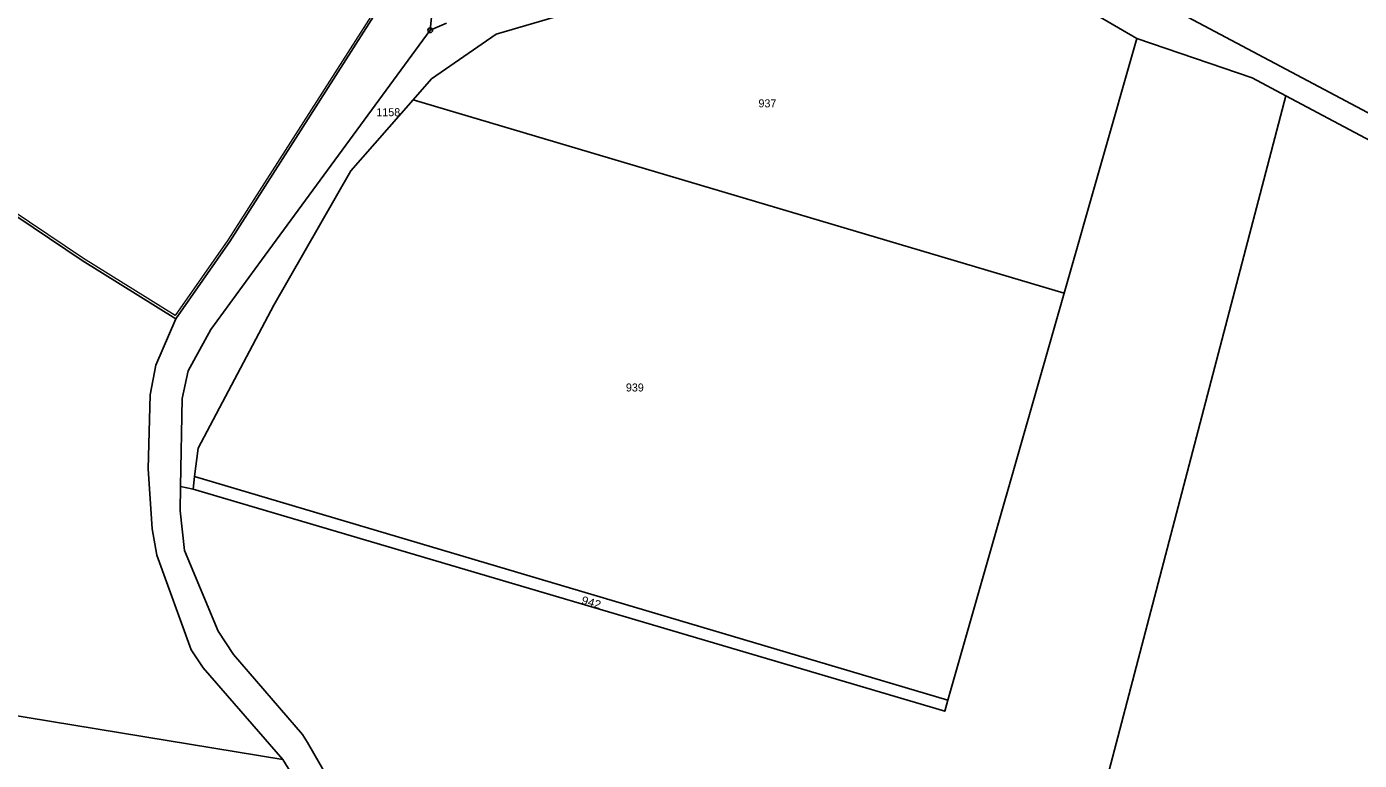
# Model space of a CAD drawing. Extents: x -758887 to -754328, y -1031688 to -1029144.
# Drawn here: x -756703.8 to -756420.8, y -1031001.8 to -1030846 of the extents above; entities that cross this region are included whole.
import ezdxf
from ezdxf.enums import TextEntityAlignment as Align

# ---------------------------------------------------------------- set-up
doc = ezdxf.new("R2010")
doc.units = 0
doc.header["$LTSCALE"] = 0.68
for name, color, linetype, lineweight in [('1', 7, 'Continuous', 25), ('4', 7, 'Continuous', 13), ('8', 7, 'Continuous', 25)]:
    doc.layers.add(name, color=color, linetype=linetype, lineweight=lineweight)
doc.layers.add('2', color=7, linetype='Continuous')

msp = doc.modelspace()

# ---------------------------------------------------------------- linework, layer by layer
at = {"layer": '1'}
for p, q in [((-756468.05, -1030848.51), (-756494.5, -1030833.17)), ((-756468.07, -1030838.25), (-756377.14, -1030886.55)), ((-756483.51, -1030902.61), (-756468.05, -1030848.51)), ((-756483.51, -1030902.61), (-756508.2, -1030989.01)), ((-756668.21, -1030941.54), (-756668.46, -1030944.22)), ((-756668.21, -1030941.54), (-756508.2, -1030989.01))]:
    msp.add_line(p, q, dxfattribs=at)
for points in [[(-756672.17, -1030908.07), (-756660.72, -1030891.63), (-756626.91, -1030838.7), (-756614.56, -1030811.5)], [(-756614.56, -1030811.5), (-756618.14, -1030846.79), (-756614.71, -1030845.27)], [(-756786.29, -1030838.32), (-756764.35, -1030847.07), (-756692.05, -1030895.68), (-756672.17, -1030908.07)], [(-756583.54, -1030841.59), (-756604.14, -1030847.6), (-756617.85, -1030857.11), (-756621.79, -1030861.59), (-756483.51, -1030902.61)], [(-756618.14, -1030846.79), (-756653.98, -1030895.62), (-756664.7, -1030910.36), (-756669.57, -1030919.12), (-756670.82, -1030924.96), (-756671.15, -1030943.68)], [(-756436.41, -1030860.73), (-756443.59, -1030856.91), (-756468.05, -1030848.51)], [(-756621.79, -1030861.59), (-756635.01, -1030876.63), (-756651.34, -1030905.15), (-756667.41, -1030935.53), (-756668.21, -1030941.54)], [(-756536.4, -1031242.21), (-756486.41, -1031051.47), (-756436.41, -1030860.73)], [(-756441.29, -1031306.34), (-756406.04, -1031176.45), (-756367.75, -1031046.99), (-756329.46, -1030917.53), (-756436.41, -1030860.73)], [(-756649.43, -1031001.63), (-756666.33, -1030982.19), (-756668.89, -1030978.32), (-756676.21, -1030958.25), (-756677.16, -1030952.66), (-756678.05, -1030939.95), (-756677.6, -1030924.23), (-756676.42, -1030917.94), (-756672.17, -1030908.07)], [(-756671.15, -1030943.68), (-756671.24, -1030948.87), (-756670.29, -1030957.24), (-756663.15, -1030974.42), (-756659.93, -1030979.33), (-756645.28, -1030996.35), (-756644.17, -1030998.05), (-756635.1, -1031013.91), (-756640.03, -1031033.6), (-756650.92, -1031058.77), (-756657.64, -1031094.12), (-756675.96, -1031141.39), (-756688.89, -1031194.83), (-756695.71, -1031217.52), (-756536.4, -1031242.21)], [(-756508.2, -1030989.01), (-756508.85, -1030991.38), (-756668.46, -1030944.22), (-756671.15, -1030943.68)], [(-756833.28, -1030963.17), (-756748.2, -1030985.46), (-756649.43, -1031001.63)], [(-756651.64, -1031045.32), (-756645.73, -1031031.66), (-756642.99, -1031020.25), (-756644.38, -1031009.77), (-756649.43, -1031001.63)]]:
    msp.add_lwpolyline(points, dxfattribs=at)
at = {"layer": '4'}
msp.add_lwpolyline([(-756660.54, -1030793.25), (-756661.38, -1030799.52), (-756662.1, -1030804.97), (-756620.96, -1030811.05), (-756615.29, -1030811.9), (-756627.35, -1030838.46), (-756661.14, -1030891.35), (-756672.31, -1030907.39), (-756691.78, -1030895.26), (-756764.12, -1030846.63), (-756786.07, -1030837.87), (-756787.28, -1030837.13)], dxfattribs=at)
at = {"layer": '8'}
for radius in [0.5, 0.0303]:
    msp.add_circle((-756618.14, -1030846.7899), radius, dxfattribs=at)

# ---------------------------------------------------------------- texts
at = {"layer": '2'}
for s, p in [('937', (-756546.529, -1030863.166)), ('1158', (-756627.04, -1030865.046)), ('939', (-756574.679, -1030923.496))]:
    msp.add_text(s, height=1.7, dxfattribs=at).set_placement(p, align=Align.CENTER)
at = {"layer": '2', "width": 1.1}
msp.add_text('942', height=1.7, rotation=344, dxfattribs=at).set_placement((-756584.1633, -1030969.0962), align=Align.CENTER)

doc.saveas('drawing.dxf')
